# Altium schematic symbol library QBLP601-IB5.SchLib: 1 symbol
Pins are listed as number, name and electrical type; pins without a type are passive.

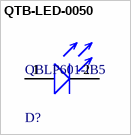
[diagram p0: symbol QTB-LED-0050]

## QTB-LED-0050
designator D?, comment QBLP601-IB5
LED BLUE CLEAR 0603 SMD; Manufacturer: QT Brightek (QTB); Lens Size: 0.8mm; Luminous Intensity: 16mcd; Test Current: 5mA; Lens Color: Colorless; Lens Style: Flat; Forward Voltage: 2.9V; Wavelength - Dominant: 470nm
footprint QBLP601-IB5-MFG
pins: 1 ANODE (+), 2 CATHODE (-)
